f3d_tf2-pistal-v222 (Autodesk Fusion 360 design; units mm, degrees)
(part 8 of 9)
sketch "Sketch178" plane through (0, 168, 0) normal (0, 1, 0) x axis (-1, 0, 0)
  line L1 (8, 20.5) -> (5, 20.5)
  line L2 (8, 24) -> (8, 20.5)
  line L3 (-8, 24) -> (8, 24)
  line L4 (-8, 20.5) -> (-8, 24)
  line L5 (-5, 20.5) -> (-8, 20.5)
  line L6 (-5, 19.3242) -> (-5, 20.5)
  line L7 (-3.5547, 19.0544) -> (-5.3513, 19.0544)
  line L8 (5.3513, 19.0544) -> (3.5547, 19.0544)
  line L9 (5, 20.5) -> (5, 19.3242)
  line L10 (8, 24) -> (-8, 24)
  line L11 (8, 20.5) -> (8, 24)
  line L12 (-8, 20.5) -> (8, 20.5)
  line L13 (-8, 24) -> (-8, 20.5)
  arc A1 centre (0, 12.4503) radius 8.5 clockwise from (-5.3513, 19.0544) to (-5, 19.3242)
  arc A2 centre (0, 12.4503) radius 7.5 clockwise from (-3.5547, 19.0544) to (3.5547, 19.0544)
  arc A3 centre (0, 12.4503) radius 8.5 clockwise from (5, 19.3242) to (5.3513, 19.0544)
  point P3 (8, 20.5)
  point P17 (8, 20.5)
  point P5 (-8, 24)
  point P15 (-8, 24)
  horizontal L10
  vertical L11
  horizontal L12
  vertical L13
  coincident P3 P17
  coincident P5 P15
extrude "Extrude183" add sketch "Sketch178" profile of L1 L2 L3 L4 L5 L10 L11 L12 L13 along normal blind 20
move_face "MoveFace284"
move_face "MoveFace285"
delete_face "DeleteFace138"
delete_face "DeleteFace139"
fillet "Fillet185" radius 0.4
move_face "MoveFace286"
sketch "Sketch179" plane through (12, 0, 0) normal (1, 0, 0) x axis (0, 1, 0)
  line L1 (170, -7.8255) -> (170, 18)
  line L2 (232.487, -7.8255) -> (170, -7.8255)
  line L3 (212.6935, 18) -> (232.487, -7.8255)
  line L4 (170, 18) -> (212.6935, 18)
  line L5 (199.0187, 27.3514) -> (199.0187, 18.4836)
  vertical L5
split "Split57"
combine "Combine152"
delete_face "DeleteFace140"
delete_face "DeleteFace141"
move_face "MoveFace287"
sketch "Sketch180" plane through (0, 208, 0) normal (0, 1, 0) x axis (-1, 0, 0)
  line L1 (8, 20.5) -> (-8, 20.5)
  line L2 (8, 24) -> (8, 20.5)
  line L3 (-8, 24) -> (8, 24)
  line L4 (-8, 20.5) -> (-8, 24)
  line L5 (5.5, 20.5) -> (5, 20.5)
  line L6 (8, 20.5) -> (5.5, 20.5)
  line L7 (-8, 20.5) -> (8, 20.5)
  line L8 (-5.5, 20.5) -> (-8, 20.5)
  line L9 (-5, 20.5) -> (-5.5, 20.5)
  line L10 (5, 20.5) -> (-5, 20.5)
  line L11 (5.5, 19.5742) -> (5.5, 20.5)
  line L12 (5.5, 20.5) -> (5.5, 19.5742)
  line L13 (5.6661, 19.4429) -> (5.6726, 19.4376)
  curve K1 (5.6726, 19.4376) -> (7.0853, 18)
  line L14 (7.0853, 18) -> (7.0945, 17.9882)
  line L15 (7.0945, 17.9882) -> (7.0853, 18)
  line L16 (-7.0853, 18) -> (-7.0945, 17.9882)
  line L17 (-7.0853, 18) -> (-7.0945, 17.9882)
  curve K2 (-7.0853, 18) -> (-5.6726, 19.4376)
  line L18 (-5.6726, 19.4376) -> (-5.6661, 19.4429)
  line L19 (-8, 20.5) -> (-8, 24)
  line L20 (-8, 24) -> (-8, 20.5)
  line L21 (-8, 24) -> (8, 24)
  line L22 (8, 24) -> (-8, 24)
  line L23 (-5.5, 20.5) -> (-5.5, 19.5742)
  line L24 (-5.5, 19.5742) -> (-5.5, 20.5)
  line L25 (-10, 18) -> (-9.9125, 18)
  line L26 (-7.0853, 18) -> (-9.9125, 18)
  line L27 (-10, 18) -> (-7.0853, 18)
  line L28 (7.0853, 18) -> (10, 18)
  line L29 (9.9125, 18) -> (7.0853, 18)
  line L30 (9.9125, 18) -> (10, 18)
  line L31 (8, 24) -> (8, 20.5)
  line L32 (8, 20.5) -> (8, 24)
  line L33 (9.974, 18) -> (-10, 18)
  line L34 (9.974, 24.7567) -> (9.974, 18)
  line L35 (-10, 24.7567) -> (9.974, 24.7567)
  line L36 (-10, 18) -> (-10, 24.7567)
  arc A1 centre (0, 12.4503) radius 9 clockwise from (5.5, 19.5742) to (5.6661, 19.4429)
  arc A2 centre (0, 12.4503) radius 9 clockwise from (5.5, 19.5742) to (7.0853, 18)
  arc A3 centre (0, 12.4503) radius 9 clockwise from (-5.6661, 19.4429) to (-5.5, 19.5742)
  arc A4 centre (0, 12.4503) radius 9 clockwise from (-7.0853, 18) to (-5.5, 19.5742)
  point P33 (-10, 18)
  point P41 (-10, 18)
  horizontal L33
  vertical L34
  horizontal L35
  vertical L36
  coincident P33 P41
extrude "Extrude184" add sketch "Sketch180" profile of L1 L5 L7 L9 L10 L11 L12 A1 L13 K1 A2 A3 A4 K2 L18 L23 L24 L33 along normal blind 8 and against normal blind 10
sketch "Sketch181" plane through (12, 0, 0) normal (1, 0, 0) x axis (0, 1, 0)
  line L1 (212.6935, 18) -> (232.487, -7.8255)
  line L2 (170, 18) -> (212.6935, 18)
  line L3 (170, 16) -> (170, 18)
  line L4 (61.1873, 16) -> (170, 16)
  line L5 (61.1873, -0.0135) -> (61.1873, 16)
  curve K1 (94.4938, -16.1797) -> (61.1873, -0.0135)
  line L6 (140.7785, -16.1797) -> (94.4938, -16.1797)
  curve K2 (160.0503, -33.0679) -> (140.7785, -16.1797)
  line L7 (180.741, -100.6968) -> (160.0503, -33.0679)
  line L8 (176.9575, -112.7565) -> (180.741, -102.825)
  line L9 (180.6935, -126.5461) -> (176.9575, -112.7565)
  line L10 (252.3821, -107.1238) -> (180.6935, -126.5461)
  curve K3 (218.6662, -36.3833) -> (252.3821, -107.1238)
  line L11 (218.6662, -22.9466) -> (218.6662, -36.3833)
  line L12 (232.2171, -10.7508) -> (218.6662, -22.9466)
  line L13 (232.487, -7.8255) -> (232.2171, -10.7508)
  line L14 (153.8679, 8.2929) -> (153.8679, 3.9459)
  line L15 (152.8679, 9.7071) -> (153.575, 9)
  line L16 (102, 10) -> (152.1608, 10)
  line L17 (100, 13) -> (100, 12)
  line L18 (156.3679, 15) -> (102, 15)
  line L19 (158.8679, 3.3459) -> (158.8679, 12.5)
  line L20 (154.8679, 2.9459) -> (158.4679, 2.9459)
  line L21 (208, -7.8255) -> (235.9291, -7.8255)
  line L22 (208, 36) -> (208, -7.8255)
  line L23 (235.9291, -7.8255) -> (208, 36)
  arc A1 centre (177.9477, -101.7609) radius 2.9891 clockwise from (180.741, -100.6968) to (180.741, -102.825)
  circle C1 centre (80, -5) radius 4
  arc A2 centre (152.8679, 8.2929) radius 1 clockwise from (153.575, 9) to (153.8679, 8.2929)
  arc A3 centre (152.1608, 9) radius 1 clockwise from (152.1608, 10) to (152.8679, 9.7071)
  arc A4 centre (102, 12) radius 2 clockwise from (102, 10) to (100, 12)
  arc A5 centre (102, 13) radius 2 clockwise from (100, 13) to (102, 15)
  arc A6 centre (156.3679, 12.5) radius 2.5 clockwise from (156.3679, 15) to (158.8679, 12.5)
  arc A7 centre (158.4679, 3.3459) radius 0.4 clockwise from (158.8679, 3.3459) to (158.4679, 2.9459)
  arc A8 centre (154.8679, 3.9459) radius 1 clockwise from (154.8679, 2.9459) to (153.8679, 3.9459)
  parallel L2 L21
  perpendicular L21 L22
extrude "Extrude185" cut sketch "Sketch181" profile of L1 L2 L21 L22 L23 against normal blind 80
move_face "MoveFace289"
delete_face "DeleteFace142"
move_face "MoveFace290"
fillet "Fillet186" radius 0.5
fillet "Fillet187" radius 0.5
fillet "Fillet188" radius 2
sketch "Sketch182" plane through (0, 61.1873, 0) normal (0, -1, 0) x axis (1, 0, 0)
  line L1 (7.0853, 18) -> (10, 18)
  line L2 (5.5, 20.5) -> (5.5, 19.5742)
  line L3 (8, 20.5) -> (5.5, 20.5)
  line L4 (8, 24) -> (8, 20.5)
  line L5 (-8, 24) -> (8, 24)
  line L6 (-8, 20.5) -> (-8, 24)
  line L7 (-5.5, 20.5) -> (-8, 20.5)
  line L8 (-5.5, 19.5742) -> (-5.5, 20.5)
  line L9 (-10, 18) -> (-7.0853, 18)
  line L10 (-12, -0.0135) -> (-12, 16)
  line L11 (12, -0.0135) -> (-12, -0.0135)
  line L12 (12, 16) -> (12, -0.0135)
  arc A1 centre (10, 16) radius 2 clockwise from (10, 18) to (12, 16)
  arc A2 centre (0, 12.4503) radius 9 clockwise from (5.5, 19.5742) to (7.0853, 18)
  arc A3 centre (0, 12.4503) radius 9 clockwise from (-7.0853, 18) to (-5.5, 19.5742)
  arc A4 centre (-10, 16) radius 2 clockwise from (-12, 16) to (-10, 18)
  circle C1 centre (0, 12.4503) radius 7
  circle C2 centre (0, 12.4503) radius 7
  circle C3 centre (0, 12.4503) radius 9
  concentric A2 C2
  concentric C2 C3
extrude "Extrude186" add sketch "Sketch182" profile of A2 A3 C1 C2 C3 along normal blind 2
chamfer "Chamfer84" distance 24.487
sketch "Sketch183" plane through (0, 0, 0) normal (1, 0, 0) x axis (0, 1, 0)
  curve K1 (156.3835, -12.3902) -> (138.0168, -12.3902)
  line L1 (157.8154, 1.7369) -> (156.3835, -12.3902)
  line L2 (154.8137, 2.0412) -> (157.8154, 1.7369)
  line L3 (153, -3) -> (154.8137, 2.0412)
  line L4 (146, -5) -> (153, -3)
  line L5 (141.1029, -4) -> (146, -5)
  circle C1 centre (132.9233, -5.754) radius 8.3656
  circle C2 centre (132.9233, -5.754) radius 3.6375
  point P2 (138.0168, -12.3902)
  point P13 (141.1029, -4)
  coincident P2 C1
  perpendicular L1 L2
  coincident C1 P13
  concentric C1 C2
extrude "Extrude187" new body sketch "Sketch183" distance 5
move "Move104"
move "Move105"
delete_face "DeleteFace143"
move_face "MoveFace291"
fillet "Fillet189" radius 2.75
delete_face "DeleteFace144"
delete_face "DeleteFace145"
fillet "Fillet190" radius 1.5
fillet "Fillet191" radius 2.25
sketch "Sketch184" plane through (0, 0, 0) normal (1, 0, 0) x axis (0, 1, 0)
  line L1 (115, -45.5944) -> (115.3754, -45.5944)
  line L2 (104.2312, -16.3305) -> (115, -45.5944)
  line L3 (160.1732, -58.5426) -> (145.9081, -60.7836)
  line L4 (170, -65) -> (160.1732, -58.5426)
  line L5 (172.2622, -64.6446) -> (170, -65)
  line L6 (157.1534, -13.7491) -> (172.2622, -64.6446)
  line L7 (104.2312, -13.7491) -> (157.1534, -13.7491)
  line L8 (104.2312, -16.3305) -> (104.2312, -13.7491)
  circle C1 centre (138.3458, -37.7027) radius 19.2949
  circle C2 centre (138.3458, -37.7027) radius 24.2882
  point P4 (115.3754, -45.5944)
  point P7 (145.9081, -60.7836)
  concentric C1 C2
  coincident C2 P4
  horizontal L1
  coincident C2 P7
  parallel L3 L5
  horizontal L7
  perpendicular L7 L8
extrude "Extrude188" new body sketch "Sketch184" distance 8
move_face "MoveFace292"
fillet "Fillet192" radius 11.5
delete_face "DeleteFace146"
combine "Combine153"
fillet "Fillet193" radius 7.5
fillet "Fillet194" radius 2
fillet "Fillet195" radius 2.5
fillet "Fillet196" radius 12
fillet "Fillet197" radius 9
sketch "Sketch185" plane through (-12, 0, 0) normal (-1, 0, 0) x axis (0, -1, 0)
  line L1 (-94.4938, -16.1797) -> (-164.2952, -16.1797)
  curve K1 (-61.1873, -0.0135) -> (-94.4938, -16.1797)
  line L2 (-61.1873, 16) -> (-61.1873, -0.0135)
  line L3 (-208.6615, 16) -> (-61.1873, 16)
  line L4 (-221.4542, 3.2073) -> (-208.6615, 16)
  line L5 (-220.6993, -4.9724) -> (-221.4542, 3.2073)
  line L6 (-206.6662, -17.6022) -> (-220.6993, -4.9724)
  line L7 (-206.6662, -40.176) -> (-206.6662, -17.6022)
  curve K2 (-206.6662, -40.176) -> (-240.729, -110.2809)
  line L8 (-189.3803, -124.1926) -> (-240.729, -110.2809)
  line L9 (-186.4094, -113.2266) -> (-189.3803, -124.1926)
  line L10 (-189.1513, -106.0289) -> (-186.4094, -113.2266)
  line L11 (-164.2952, -16.1797) -> (-189.2884, -97.8715)
  line L12 (-156.6179, 2.9459) -> (-154.8679, 2.9459)
  line L13 (-158.8679, 12.5) -> (-158.8679, 5.1959)
  line L14 (-102, 15) -> (-156.3679, 15)
  line L15 (-100, 12) -> (-100, 13)
  line L16 (-150.7288, 10) -> (-102, 10)
  line L17 (-153.0624, 8.8055) -> (-152.6733, 9.1945)
  line L18 (-153.8679, 3.9459) -> (-153.8679, 6.8609)
  line L19 (-164.2952, -16.1797) -> (-94.4938, -16.1797)
  line L20 (-189.2884, -97.8715) -> (-164.2952, -16.1797)
  curve K3 (-171.2455, -38.897) -> (-143.3956, -16.1797)
  curve K4 (-147.7912, -17.3594) -> (-139, -15)
  arc A1 centre (-177.9477, -101.7609) radius 11.9891 clockwise from (-189.1513, -106.0289) to (-189.2884, -97.8715)
  circle C1 centre (-80, -5) radius 4
  arc A2 centre (-156.6179, 5.1959) radius 2.25 clockwise from (-156.6179, 2.9459) to (-158.8679, 5.1959)
  arc A3 centre (-156.3679, 12.5) radius 2.5 clockwise from (-158.8679, 12.5) to (-156.3679, 15)
  arc A4 centre (-102, 13) radius 2 clockwise from (-102, 15) to (-100, 13)
  arc A5 centre (-102, 12) radius 2 clockwise from (-100, 12) to (-102, 10)
  arc A6 centre (-150.7288, 7.25) radius 2.75 clockwise from (-152.6733, 9.1945) to (-150.7288, 10)
  arc A7 centre (-151.1179, 6.8609) radius 2.75 clockwise from (-153.8679, 6.8609) to (-153.0624, 8.8055)
  arc A8 centre (-154.8679, 3.9459) radius 1 clockwise from (-153.8679, 3.9459) to (-154.8679, 2.9459)
  point P42 (-143.3956, -16.1797)
  point P45 (-171.2455, -38.897)
  coincident L19 P42
  coincident L20 P45
  midpoint P42 K4
extrude "Extrude189" new body sketch "Sketch185" profile of L1 L11 L19 L20 K3 against normal blind 4
mirror "Mirror43" mirrorStitchTolerance 0.1
combine "Combine154"
fillet "Fillet198" radius 2.5
fillet "Fillet199" radius 15
chamfer "Chamfer85" distance 1
move_face "MoveFace293"
move_face "MoveFace294"
fillet "Fillet200" radius 4
fillet "Fillet201" radius 1
fillet "Fillet202" radius 1
move_face "MoveFace295"
sketch "Sketch186" plane through (0, 0, 0) normal (1, 0, 0) x axis (0, 1, 0)
  line L1 (152.446, 6.5702) -> (139.9456, 2.0072)
  line L2 (159.6229, 4.8892) -> (152.446, 6.5702)
  curve K1 (155, -30) -> (159.6229, 4.8892)
  curve K2 (143.3256, -19.8355) -> (137.9113, -11.6209)
  line L3 (155, -30) -> (143.3256, -19.8355)
  circle C1 centre (133.5549, -4.0047) radius 3.6375
  circle C2 centre (133.5549, -4.0047) radius 8.7741
  point P5 (139.9456, 2.0072)
  point P10 (137.9113, -11.6209)
  concentric C1 C2
  coincident C2 P5
  coincident C2 P10
extrude "Extrude190" cut sketch "Sketch186" distance 5.2
delete_face "DeleteFace147"
delete_face "DeleteFace148"
sketch "Sketch187" plane through (-5, 0, 0) normal (-1, 0, 0) x axis (0, -1, 0)
  line L1 (-146.65, -3.7075) -> (-141.7908, -2.5372)
  line L2 (-153.7155, -1.953) -> (-146.65, -3.7075)
  line L3 (-155.7041, 3.0218) -> (-153.7155, -1.953)
  line L4 (-158.6933, 2.6129) -> (-155.7041, 3.0218)
  line L5 (-156.7692, -11.4556) -> (-158.6933, 2.6129)
  curve K1 (-138.4137, -10.8146) -> (-156.7692, -11.4556)
  line L6 (-143, -18) -> (-160, -12)
  line L7 (-145.0135, -29) -> (-145.0135, -17.2894)
  line L8 (-139.9494, -46.8713) -> (-145.0135, -29)
  line L9 (-146.9651, -39.243) -> (-139.9494, -46.8713)
  line L10 (-154.4003, -23.1447) -> (-146.9651, -39.243)
  line L11 (-155.5267, -13.5788) -> (-154.4003, -23.1447)
  line L12 (-154.4003, -41.7536) -> (-158.6986, -12.4593)
  line L13 (-143.3923, -50.4441) -> (-154.4003, -41.7536)
  line L14 (-133.6396, -50.4441) -> (-143.3923, -50.4441)
  line L15 (-128.9829, -44.5456) -> (-133.6396, -50.4441)
  line L16 (-137.5986, -32.2906) -> (-128.9829, -44.5456)
  line L17 (-143, -18) -> (-137.5986, -32.2906)
  circle C1 centre (-133.5549, -4.0047) radius 3.6375
  arc A1 centre (-133.5549, -4.0047) radius 8.3656 clockwise from (-141.7908, -2.5372) to (-138.4137, -10.8146)
  point P12 (-145.0135, -17.2894)
  point P17 (-155.5267, -13.5788)
  point P18 (-158.6986, -12.4593)
  coincident L6 P12
  vertical L7
  coincident L6 P17
  coincident L6 P18
  horizontal L14
  perpendicular L13 L15
extrude "Extrude191" cut sketch "Sketch187" profile of K1 L6 L7 L8 L9 L10 L11 L12 L13 L14 L15 L16 L17 against normal blind 10
fillet "Fillet203" radius 18.5
fillet "Fillet204" radius 55.5
fillet "Fillet205" radius 2.75
fillet "Fillet206" radius 14
fillet "Fillet207" radius 2
fillet "Fillet208" radius 0.5
fillet "Fillet209" radius 2
fillet "Fillet210" radius 2
fillet "Fillet211" radius 317
fillet "Fillet212" radius 2.5
sketch "Sketch188" plane through (0, 15.8076, -43.3059) normal (0, 0.3429, -0.9394) x axis (-1, 0, 0)
  line L1 (5.2, 146.9606) -> (5.2, 132.1495)
  line L2 (4.4969, 146.9606) -> (5.2, 146.9606)
  line L3 (-5.2, 146.9606) -> (-4.4969, 146.9606)
  line L4 (-5.2, 132.1495) -> (-5.2, 146.9606)
  line L5 (5.2, 132.1495) -> (-5.2, 132.1495)
  line L6 (5.2, 138.788) -> (-5.2, 138.788)
  line L7 (5.2, 145.212) -> (5.2, 138.788)
  line L8 (-5.2, 145.212) -> (5.2, 145.212)
  line L9 (-5.2, 138.788) -> (-5.2, 145.212)
  line L10 (5.2, 145.212) -> (-5.2, 138.788)
  line L11 (-5.2, 145.212) -> (5.2, 138.788)
  line L12 (5.2, 147.6213) -> (-5.2, 147.6213)
  line L13 (5.2, 140.3787) -> (5.2, 147.6213)
  line L14 (-5.2, 140.3787) -> (5.2, 140.3787)
  line L15 (-5.2, 147.6213) -> (-5.2, 140.3787)
  line L16 (5.2, 140.3787) -> (-5.2, 147.6213)
  line L17 (-5.2, 140.3787) -> (5.2, 147.6213)
  closed curve K1 centre (0, 162.6054)
  point P13 (0, 142)
  point P9 (-5.2, 138.788)
  point P18 (0, 144)
  horizontal L6
  perpendicular L6 L7
  parallel L6 L8
  parallel L7 L9
  coincident L10 P13
  coincident L11 P13
  coincident L4 P9
  horizontal L12
  perpendicular L12 L13
  parallel L12 L14
  parallel L13 L15
  coincident L16 P18
  coincident L17 P18
extrude "Extrude192" cut sketch "Sketch188" profile of L1 L2 K1 L3 L4 L7 L8 L9 L12 L13 L14 L15 against normal blind 6
fillet "Fillet213" radius 2
sketch "Sketch189" plane through (0, 208, 0) normal (0, 1, 0) x axis (-1, 0, 0)
  line L1 (11.8874, 16.6615) -> (-11.8874, 16.6615)
  line L2 (7.0853, 18) -> (10, 18)
  line L3 (5.5, 20.5) -> (5.5, 19.5742)
  line L4 (8, 20.5) -> (5.5, 20.5)
  line L5 (8, 24) -> (8, 20.5)
  line L6 (-8, 24) -> (8, 24)
  line L7 (-8, 20.5) -> (-8, 24)
  line L8 (-5.5, 20.5) -> (-8, 20.5)
  line L9 (-5.5, 19.5742) -> (-5.5, 20.5)
  curve K1 (-5.6726, 19.4376) -> (-7.0853, 18)
  line L10 (-10, 18) -> (-7.0853, 18)
  line L11 (-3, 11) -> (3, 11)
  line L12 (-3, 37) -> (-3, 11)
  line L13 (3, 37) -> (-3, 37)
  line L14 (3, 11) -> (3, 37)
  line L15 (-3, 37) -> (3, 11)
  line L16 (3, 37) -> (-3, 11)
  arc A1 centre (10, 16) radius 2 clockwise from (10, 18) to (11.8874, 16.6615)
  arc A2 centre (0, 12.4503) radius 9 clockwise from (5.5, 19.5742) to (7.0853, 18)
  arc A3 centre (0, 12.4503) radius 9 clockwise from (-5.6726, 19.4376) to (-5.5, 19.5742)
  arc A4 centre (-10, 16) radius 2 clockwise from (-11.8874, 16.6615) to (-10, 18)
  point P24 (0, 24)
  horizontal L11
  perpendicular L11 L12
  parallel L11 L13
  parallel L12 L14
  coincident L15 P24
  coincident L16 P24
  midpoint L6 P24
extrude "Extrude193" cut sketch "Sketch189" profile of L1 L6 L11 L12 L13 L14 along normal blind 25 and against normal blind 20
chamfer "Chamfer86" distance 0.5
chamfer "Chamfer87" distance 0.5
move_face "MoveFace296"
sketch "Sketch190" plane through (0, 0, 0) normal (1, 0, 0) x axis (0, 1, 0)
  line L1 (232.6325, -6.7081) -> (207, 27)
  line L2 (100, -6.7081) -> (232.6325, -6.7081)
  curve K1 (70.1883, 6.3275) -> (100, -6.7081)
  curve K2 (63.1691, 6.3275) -> (77.2075, 6.3275)
  line L3 (61, 6.3275) -> (70.1883, 6.3275)
  line L4 (61, 27) -> (61, 6.3275)
  line L5 (213, 27) -> (61, 27)
  point P7 (70.1883, 6.3275)
  point P2 (207, 27)
  horizontal L2
  midpoint P7 K2
  perpendicular L3 L4
  perpendicular L4 L5
  coincident P2 L5
extrude "Extrude194" new body sketch "Sketch190" profile of L1 L2 K1 L3 L4 L5 distance 14
shell "Shell2" innerThickness 1.5
fillet "Fillet214" radius 12
fillet "Fillet215" radius 2.5
move_face "MoveFace297"
fillet "Fillet216" radius 2.5
fillet "Fillet217" radius 4
fillet "Fillet218" radius 0.5
fillet "Fillet219" radius 1
copy_paste_bodies "CopyPasteBodies15"
offset_faces "OffsetFaces30" distance 1
offset_faces "OffsetFaces31" distance 1
offset_faces "OffsetFaces32" distance 1
sketch "Sketch191" plane through (0, 60, 0) normal (0, -1, 0) x axis (1, 0, 0)
  line L1 (-3, 27.5) -> (3, 27.5)
  line L2 (-14.5, 8.8275) -> (-14.5, 16)
  line L3 (-13, 8.8275) -> (-14.5, 8.8275)
  line L4 (-13, 13.5) -> (-13, 8.8275)
  line L5 (0.5, 26) -> (-0.5, 26)
  line L6 (13, 8.8275) -> (13, 13.5)
  line L7 (14.5, 8.8275) -> (13, 8.8275)
  line L8 (14.5, 16) -> (14.5, 8.8275)
  line L9 (-8.2, 24.2) -> (-8.2, 20.2499)
  line L10 (8.2, 24.2) -> (-8.2, 24.2)
  line L11 (8.2, 20.2499) -> (8.2, 24.2)
  line L12 (-8.2, 24.2) -> (8.2, 20.2499)
  line L13 (8.2, 24.2) -> (-8.2, 20.2499)
  line L14 (8, 24) -> (8, 20.5)
  line L15 (-8, 20.5) -> (-8, 24)
  line L16 (-8, 24) -> (8, 24)
  line L17 (-8.2, 20.3) -> (8.2, 20.3)
  line L18 (3.5, 20.5) -> (-3.5, 20.5)
  line L19 (5.5, 20.5) -> (3.5, 20.5)
  line L20 (8, 20.5) -> (5.5, 20.5)
  line L21 (5.5, 20.5) -> (8, 20.5)
  line L22 (5.5, 20.5) -> (5, 20.5)
  line L23 (-5, 20.5) -> (5, 20.5)
  line L24 (-5, 20.5) -> (-5.5, 20.5)
  line L25 (-8, 20.5) -> (-5.5, 20.5)
  line L26 (-5.5, 20.5) -> (-8, 20.5)
  line L27 (-3.5, 20.5) -> (-5.5, 20.5)
  line L28 (-5.7, 19) -> (-5.7, 20.3)
  line L29 (5.7, 19) -> (5.7, 20.3)
  line L30 (-5.5, 19.5742) -> (-5.5, 20.5)
  line L31 (5.5, 20.5) -> (5.5, 19.5742)
  line L32 (17.4528, 18.2) -> (-12.686, 18.2)
  line L33 (18.2375, 18.4672) -> (17.4528, 18.2)
  line L34 (7.0853, 18) -> (10, 18)
  line L35 (10, 18.2) -> (5.7, 19.65)
  line L36 (-10, 18) -> (-7.0853, 18)
  line L37 (-10, 18.2) -> (-5.7, 19.65)
  arc A1 centre (3, 16) radius 11.5 clockwise from (3, 27.5) to (14.5, 16)
  arc A2 centre (-3, 16) radius 11.5 clockwise from (-14.5, 16) to (-3, 27.5)
  arc A3 centre (-0.5, 13.5) radius 12.5 clockwise from (-13, 13.5) to (-0.5, 26)
  arc A4 centre (0.5, 13.5) radius 12.5 clockwise from (0.5, 26) to (13, 13.5)
  circle C1 centre (0, 12.4503) radius 9
  circle C2 centre (0, 12.4503) radius 9.2
  point P22 (0, 22.225)
  point P27 (8.2, 20.3)
  point P28 (-8.2, 20.3)
  point P37 (-5.7, 20.3)
  point P39 (5.7, 20.3)
  point P52 (5.7, 19.65)
  point P53 (10, 18.2)
  point P56 (-5.7, 19.65)
  point P57 (-10, 18.2)
  point P29 (-3.5, 20.5)
  parallel L9 L11
  coincident L12 P22
  coincident L13 P22
  coincident L11 P27
  coincident L9 P28
  perpendicular L9 L17
  coincident L17 P37
  perpendicular L17 L28
  coincident L17 P39
  perpendicular L17 L29
  concentric C1 C2
  horizontal L32
  midpoint L29 P52
  coincident L32 P53
  midpoint L28 P56
  coincident L32 P57
  dimension "d1533" distance L11 L14 = 0.2
  dimension "d1534" distance L9 L15 = 0.2
  dimension "d1535" distance L10 L16 = 0.2
  dimension "d1536" distance L17 P29 = 0.2
  dimension "d1537" distance L28 L30 = 0.2
  dimension "d1538" distance L29 L31 = 0.2
  dimension "d1539" distance C1 C2 = 0.2
  dimension "d1540" distance L32 L34 = 0.2
extrude "Extrude195" new body sketch "Sketch191" profile of A3 L5 A4 L9 L10 L11 L17 L28 L29 C2 L32 L35 L37 against normal blind 147
split "Split58"
split "Split59"
remove_body "RemoveBody87"
remove_body "RemoveBody88"
combine "Combine155"
delete_face "DeleteFace149"
delete_face "DeleteFace150"
chamfer "Chamfer88" distance 2
chamfer "Chamfer89" distance 0.5
sketch "Sketch192" plane through (0, 0, 0) normal (1, 0, 0) x axis (0, 1, 0)
  line L1 (200, 11.142) -> (154, 11.142)
  line L2 (200, 17.483) -> (200, 11.142)
  line L3 (154, 17.483) -> (200, 17.483)
  line L4 (154, 11.142) -> (154, 17.483)
  line L5 (207, 24.2) -> (207.2241, 24.2)
  line L6 (60, 24.2) -> (207, 24.2)
  line L7 (207, 24.2) -> (60, 24.2)
  line L8 (207, 24.2) -> (207.2241, 24.2)
  line L9 (188.1902, 24.2) -> (207, 24.2)
  line L10 (188.1902, 11.142) -> (188.1902, 24.2)
  line L11 (207, 11.142) -> (188.1902, 11.142)
  line L12 (207, 24.2) -> (207, 11.142)
  point P11 (188.1902, 11.142)
  point P7 (207, 24.2)
  point P9 (207, 24.2)
  horizontal L1
  vertical L2
  horizontal L3
  vertical L4
  horizontal L9
  vertical L10
  horizontal L11
  vertical L12
  coincident L1 P11
  coincident P7 P9
extrude "Extrude196" new body sketch "Sketch192" profile of L1 L2 L3 L4 L6 L7 L9 L10 L11 L12 distance 3
sketch "Sketch193" plane through (-15, 0, 0) normal (-1, 0, 0) x axis (0, -1, 0)
  line L1 (-227.2272, -6.2081) -> (-210.3395, 16)
  line L2 (-101.5272, -6.2081) -> (-227.2272, -6.2081)
  curve K1 (-101.5272, -6.2081) -> (-99.7709, -5.1649)
  curve K2 (-99.7709, -5.1649) -> (-70.1883, 6.8275)
  line L3 (-62.5, 6.8275) -> (-70.1883, 6.8275)
  line L4 (-60.5, 16) -> (-60.5, 8.8275)
  line L5 (-210.3395, 16) -> (-60.5, 16)
  line L6 (-100.4605, 14.9736) -> (-159.0253, 14.9736)
  line L7 (-159.0253, 14.9736) -> (-159.0253, 2.7844)
  line L8 (-98.1178, 2.9961) -> (-98.1314, 6.9148)
  line L9 (-100.4605, 14.9736) -> (-98.1314, 6.9148)
  line L10 (-98.1178, 2.9961) -> (-159.0253, 2.7844)
  arc A1 centre (-62.5, 8.8275) radius 2 clockwise from (-60.5, 8.8275) to (-62.5, 6.8275)
  horizontal L6
  vertical L7
  perpendicular L8 L10
split "Split60"
fillet "Fillet220" radius 2
fillet "Fillet221" radius 2
fillet "Fillet222" radius 2.5
fillet "Fillet223" radius 2.25
move_face "MoveFace298"
move_face "MoveFace299"
chamfer "Chamfer90" distance 0.5
split "Split61"
delete_face "DeleteFace151"
fillet "Fillet224" radius 59
move_face "MoveFace300"
move_face "MoveFace301"
move_face "MoveFace302"
sketch "Sketch194" plane through (0, 0, 0) normal (-1, 0, 0) x axis (0, -1, 0)
  line L1 (-212.6009, 10.6464) -> (-211.7473, 11)
  line L2 (-231.0728, -7.8255) -> (-212.6009, 10.6464)
  line L3 (-231.3905, -7.8255) -> (-231.0728, -7.8255)
  curve K1 (-231.3905, -7.8255) -> (-232.3863, -8.9174)
  line L4 (-232.2171, -10.7508) -> (-232.3863, -8.9174)
  line L5 (-218.6662, -22.9466) -> (-232.2171, -10.7508)
  line L6 (-218.6662, -36.3833) -> (-218.6662, -22.9466)
  curve K2 (-252.0162, -106.1931) -> (-218.6662, -36.3833)
  line L7 (-251.4169, -107.3853) -> (-252.0162, -106.1931)
  line L8 (-235.1318, -111.7973) -> (-251.4169, -107.3853)
  line L9 (-201.3197, 10.517) -> (-233.9044, -111.0909)
  line L10 (-201.6902, 11) -> (-201.3197, 10.517)
  line L11 (-211.7473, 11) -> (-201.6902, 11)
  line L12 (-204.3927, -0.9518) -> (-224.1991, -0.9518)
  line L13 (-204.3927, -0.9518) -> (-212.5827, -31.5171)
  line L14 (-211.4843, -31.8114) -> (-212.5827, -31.5171)
  line L15 (-212.4984, -35.596) -> (-211.4843, -31.8114)
  line L16 (-215.7362, -34.7285) -> (-212.4984, -35.596)
  line L17 (-207.5956, -4.3472) -> (-215.7362, -34.7285)
  line L18 (-213.8018, -4.3472) -> (-207.5956, -4.3472)
  line L19 (-225.4416, -16.8487) -> (-213.8018, -4.3472)
  line L20 (-217, -17) -> (-213.8018, -4.3472)
  line L21 (-217, -39) -> (-217, -17)
  line L22 (-214.7493, -39.6031) -> (-217, -39)
  arc A1 centre (-234.8703, -110.8321) radius 1 clockwise from (-233.9044, -111.0909) to (-235.1318, -111.7973)
  point P17 (-224.1991, -0.9518)
  point P18 (-204.3927, -0.9518)
  point P19 (-212.5827, -31.5171)
  point P25 (-225.4416, -16.8487)
  point P28 (-214.7493, -39.6031)
  coincident L2 P17
  coincident L9 P18
  horizontal L12
  coincident L9 P19
  parallel L9 L13
  perpendicular L9 L14
  perpendicular L14 L15
  perpendicular L15 L16
  perpendicular L16 L17
  horizontal L18
  midpoint L5 P25
  parallel L6 L21
  coincident L9 P28
  perpendicular L9 L22
extrude "Extrude197" cut sketch "Sketch194" profile of L9 L16 L17 L18 L20 L21 L22 distance 5
sketch "Sketch195" plane through (0, 60, 0) normal (0, -1, 0) x axis (1, 0, 0)
  line L1 (8.2, 24.2) -> (-8.2, 24.2)
  line L2 (8.2, 20.3) -> (8.2, 24.2)
  line L3 (5.7, 20.3) -> (8.2, 20.3)
  line L4 (5.7, 19.6718) -> (5.7, 20.3)
  line L5 (10, 18.2) -> (5.7476, 19.6339)
  line L6 (12.0827, 18.2) -> (10, 18.2)
  line L7 (13, 8.8275) -> (13, 13.5)
  line L8 (14.5, 8.8275) -> (13, 8.8275)
  line L9 (14.5, 16) -> (14.5, 8.8275)
  line L10 (-3, 27.5) -> (3, 27.5)
  line L11 (-14.5, 8.8275) -> (-14.5, 16)
  line L12 (-13, 8.8275) -> (-14.5, 8.8275)
  line L13 (-13, 13.5) -> (-13, 8.8275)
  line L14 (-10, 18.2) -> (-12.0827, 18.2)
  line L15 (-5.7476, 19.6339) -> (-10, 18.2)
  line L16 (-5.7, 20.3) -> (-5.7, 19.6718)
  line L17 (-8.2, 20.3) -> (-5.7, 20.3)
  line L18 (-8.2, 24.2) -> (-8.2, 20.3)
  line L19 (-8.2, 18.4441) -> (-8.2, 20.3)
  line L20 (8.2, 18.3692) -> (8.2, 20.3)
  arc A1 centre (0, 12.4503) radius 9.2 clockwise from (5.7, 19.6718) to (5.7476, 19.6339)
  arc A2 centre (0.5, 13.5) radius 12.5 clockwise from (12.0827, 18.2) to (13, 13.5)
  arc A3 centre (3, 16) radius 11.5 clockwise from (3, 27.5) to (14.5, 16)
  arc A4 centre (-3, 16) radius 11.5 clockwise from (-14.5, 16) to (-3, 27.5)
  arc A5 centre (-0.5, 13.5) radius 12.5 clockwise from (-13, 13.5) to (-12.0827, 18.2)
  arc A6 centre (0, 12.4503) radius 9.2 clockwise from (-5.7476, 19.6339) to (-5.7, 19.6718)
  point P30 (-8.2, 20.3)
  point P31 (-8.2, 20.3)
  point P4 (8.2, 20.3)
  point P33 (8.2, 20.3)
  coincident P30 P31
  perpendicular L17 L19
  coincident P4 P33
  perpendicular L3 L20
extrude "Extrude198" cut sketch "Sketch195" profile of L3 L4 A1 L5 L15 A6 L16 L17 L19 L20 against normal blind 1.187
fillet "Fillet225" radius 0.5
delete_face "DeleteFace152"
delete_face "DeleteFace153"
delete_face "DeleteFace154"
delete_face "DeleteFace155"
fillet "Fillet226" radius 5
fillet "Fillet227" radius 9.5
fillet "Fillet228" radius 1
fillet "Fillet229" radius 1
fillet "Fillet230" radius 0.5
fillet "Fillet231" radius 0.5
delete_face "DeleteFace156"
delete_face "DeleteFace157"
chamfer "Chamfer91" distance 8
sketch "Sketch196" plane through (0, 60, 0) normal (0, -1, 0) x axis (1, 0, 0)
  line L1 (7, 28) -> (15, 20)
  line L2 (-7, 28) -> (7, 28)
  line L3 (-15, 20) -> (-7, 28)
  line L4 (-15, 8.8275) -> (-15, 20)
  line L5 (-12.5, 8.8275) -> (-15, 8.8275)
  line L6 (-12.5, 13.5) -> (-12.5, 8.8275)
  line L7 (-10, 18.2) -> (-11.5413, 18.2)
  line L8 (-8.2, 18.807) -> (-10, 18.2)
  line L9 (-8.2, 24.2) -> (-8.2, 18.807)
  line L10 (8.2, 24.2) -> (-8.2, 24.2)
  line L11 (8.2, 18.807) -> (8.2, 24.2)
  line L12 (10, 18.2) -> (8.2, 18.807)
  line L13 (11.5413, 18.2) -> (10, 18.2)
  line L14 (12.5, 8.8275) -> (12.5, 13.5)
  line L15 (15, 8.8275) -> (12.5, 8.8275)
  line L16 (15, 20) -> (15, 8.8275)
  arc A1 centre (-0.5, 13.5) radius 12 clockwise from (-12.5, 13.5) to (-11.5413, 18.2)
  arc A2 centre (0.5, 13.5) radius 12 clockwise from (11.5413, 18.2) to (12.5, 13.5)
  circle C1 centre (0, 40) radius 13.0036
extrude "Extrude199" cut sketch "Sketch196" profile of L2 C1 against normal blind 160
chamfer "Chamfer92" distance 5
fillet "Fillet232" radius 10
fillet "Fillet233" radius 0.5
fillet "Fillet234" radius 0.5
sketch "Sketch197" plane through (-12, 0, 0) normal (-1, 0, 0) x axis (0, -1, 0)
  line L1 (-221.2152, 0.6179) -> (-205.8331, 16)
  line L2 (-220.6993, -4.9724) -> (-221.2152, 0.6179)
  line L3 (-206.6662, -17.6022) -> (-220.6993, -4.9724)
  line L4 (-206.6662, -40.176) -> (-206.6662, -17.6022)
  curve K1 (-206.6662, -40.176) -> (-240.3598, -109.3449)
  line L5 (-189.1188, -123.2274) -> (-240.3598, -109.3449)
  line L6 (-186.4094, -113.2266) -> (-189.1188, -123.2274)
  line L7 (-189.1513, -106.0289) -> (-186.4094, -113.2266)
  line L8 (-169.5112, -33.2283) -> (-189.2884, -97.8715)
  curve K2 (-169.5112, -33.2283) -> (-143.7253, -13.6797)
  line L9 (-94.4207, -13.6797) -> (-143.7253, -13.6797)
  curve K3 (-94.4207, -13.6797) -> (-61.1873, 4.4251)
  line L10 (-61.1873, 16) -> (-61.1873, 4.4251)
  line L11 (-205.8331, 16) -> (-61.1873, 16)
  line L12 (-152.7089, 8.4519) -> (-152.3198, 8.841)
  line L13 (-153.3679, 3.9459) -> (-153.3679, 6.8609)
  line L14 (-156.6179, 2.4459) -> (-154.8679, 2.4459)
  line L15 (-159.3679, 12.5) -> (-159.3679, 5.1959)
  line L16 (-102, 15.5) -> (-156.3679, 15.5)
  line L17 (-99.5, 12) -> (-99.5, 13)
  line L18 (-150.7288, 9.5) -> (-102, 9.5)
  line L19 (-207.9923, -10) -> (-210, -10)
  line L20 (-156.9952, -10) -> (-207.9923, -10)
  line L21 (-162.573, -10) -> (-190.5399, -101.9622)
  line L22 (-189.1513, -109.6278) -> (-190.5399, -101.9622)
  line L23 (-191.7368, -118.1293) -> (-189.1513, -109.6278)
  line L24 (-242.7117, -102.6271) -> (-191.7368, -118.1293)
  line L25 (-210.775, -33.2696) -> (-242.7117, -102.6271)
  line L26 (-210, -10) -> (-210.775, -33.2696)
  circle C1 centre (-80, -5) radius 4
  arc A1 centre (-177.9477, -101.7609) radius 11.9891 clockwise from (-189.1513, -106.0289) to (-189.2884, -97.8715)
  arc A2 centre (-150.7288, 7.25) radius 2.25 clockwise from (-152.3198, 8.841) to (-150.7288, 9.5)
  arc A3 centre (-151.1179, 6.8609) radius 2.25 clockwise from (-153.3679, 6.8609) to (-152.7089, 8.4519)
  arc A4 centre (-154.8679, 3.9459) radius 1.5 clockwise from (-153.3679, 3.9459) to (-154.8679, 2.4459)
  arc A5 centre (-156.6179, 5.1959) radius 2.75 clockwise from (-156.6179, 2.4459) to (-159.3679, 5.1959)
  arc A6 centre (-156.3679, 12.5) radius 3 clockwise from (-159.3679, 12.5) to (-156.3679, 15.5)
  arc A7 centre (-102, 13) radius 2.5 clockwise from (-102, 15.5) to (-99.5, 13)
  arc A8 centre (-102, 12) radius 2.5 clockwise from (-99.5, 12) to (-102, 9.5)
  point P44 (-162.573, -10)
  horizontal L19
  parallel L19 L20
  coincident L20 P44
  parallel L21 L23
  perpendicular L23 L24
extrude "Extrude200" new body sketch "Sketch197" profile of L3 L4 K1 A1 L19 L20 L21 L22 L23 L24 L25 L26 along normal blind 1 and against normal blind 1
combine "Combine156"
fillet "Fillet235" radius 4.5
fillet "Fillet236" radius 2
move_face "MoveFace303"
fillet "Fillet237" radius 7
extrude "Extrude201" add of existing geometry blind 1
delete_face "DeleteFace158"
fillet "Fillet238" radius 2
sketch "Sketch198" plane through (-14, 0, 0) normal (-1, 0, 0) x axis (0, -1, 0)
  line L1 (-191.5572, -110.665) -> (-193.4854, -117.0054)
  line L2 (-192.5941, -101.8429) -> (-191.421, -108.319)
  line L3 (-166.2531, -15.2274) -> (-192.5941, -101.8429)
  line L4 (-205.6474, -12) -> (-168.645, -12)
  line L5 (-208.7895, -33.7396) -> (-208.146, -14.4168)
  line L6 (-241.0868, -103.8801) -> (-208.7895, -33.7396)
  line L7 (-193.4854, -117.0054) -> (-241.0868, -103.8801)
  arc A1 centre (-196.3409, -109.2102) radius 5 clockwise from (-191.421, -108.319) to (-191.5572, -110.665)
  arc A2 centre (-168.645, -14.5) radius 2.5 clockwise from (-168.645, -12) to (-166.2531, -15.2274)
  arc A3 centre (-205.6474, -14.5) radius 2.5 clockwise from (-208.146, -14.4168) to (-205.6474, -12)
  circle C1 centre (-205.3592, -68.1791) radius 13.0992
extrude "Extrude202" cut sketch "Sketch198" profile of C1 against normal blind 1
chamfer "Chamfer93" distance 1
fillet "Fillet239" radius 0.5
offset_faces "OffsetFaces33" distance -0.2
sketch "Sketch199" plane through (5.2, 0, 0) normal (-1, 0, 0) x axis (0, -1, 0)
  line L1 (-153.3679, 3.9459) -> (-153.3679, 6.8609)
  line L2 (-156.6179, 2.4459) -> (-154.8679, 2.4459)
  line L3 (-159.7699, -1.0651) -> (-158.9914, 1.8404)
  curve K1 (-159.7699, -1.0651) -> (-159.3334, -8.2801)
  curve K2 (-157.6396, -37.9016) -> (-159.3334, -8.2801)
  curve K3 (-141.7435, -14.4954) -> (-139.5542, -18.4457)
  curve K4 (-141.7435, -14.4954) -> (-137.9113, -11.6209)
  line L4 (-147.6758, 4.8289) -> (-139.9456, 2.0072)
  line L5 (-147.3249, 5.7903) -> (-147.6758, 4.8289)
  curve K5 (-144.9641, 7.7641) -> (-147.3249, 5.7903)
  line L6 (-153.1786, 7.7641) -> (-144.9641, 7.7641)
  arc A1 centre (-151.1179, 6.8609) radius 2.25 clockwise from (-153.3679, 6.8609) to (-153.1786, 7.7641)
  arc A2 centre (-154.8679, 3.9459) radius 1.5 clockwise from (-153.3679, 3.9459) to (-154.8679, 2.4459)
  arc A3 centre (-156.6179, 5.1959) radius 2.75 clockwise from (-156.6179, 2.4459) to (-158.0764, 2.8646)
  arc A4 centre (-157.5191, 1.4459) radius 1.5242 clockwise from (-158.9914, 1.8404) to (-158.0764, 2.8646)
  arc A5 centre (-138.3458, -37.7027) radius 19.2949 clockwise from (-157.6396, -37.9016) to (-139.5542, -18.4457)
  arc A6 centre (-133.5549, -4.0047) radius 8.7741 clockwise from (-139.9456, 2.0072) to (-137.9113, -11.6209)
  circle C1 centre (-133.5549, -4.0047) radius 3.2417
  concentric A6 C1
extrude "Extrude203" new body sketch "Sketch199" profile of C1 along normal blind 5.2 bodies "Spacer"
mirror "Mirror44" mirrorStitchTolerance 0.1
extrude "Extrude204" add of existing geometry blind 2
extrude "Extrude205" add of existing geometry blind 2
sketch "Sketch200" plane through (-7.2, 0, 0) normal (-1, 0, 0) x axis (0, -1, 0)
  circle C1 centre (-133.5549, -4.0047) radius 3.3487
extrude "Extrude206" cut sketch "Sketch200" against normal blind 14.4
remove_body "RemoveBody89"
remove_body "RemoveBody90"
remove_body "RemoveBody91"
remove_body "RemoveBody92"
remove_body "RemoveBody93"
sketch "Sketch201" plane through (0, 0, 0) normal (1, 0, 0) x axis (0, 1, 0)
  line L1 (235.4811, 5) -> (235.4811, 8.5401)
  line L2 (227.3196, 5) -> (235.4811, 5)
  line L3 (223, 0) -> (227.3196, 5)
  line L4 (215, 3) -> (223, 0)
  line L5 (220.6186, 9.5036) -> (215, 3)
  line L6 (235.4811, 9.5036) -> (220.6186, 9.5036)
  line L7 (235.4811, 8.5401) -> (235.4811, 9.5036)
  vertical L1
  perpendicular L1 L2
  parallel L3 L5
  parallel L2 L6
  perpendicular L6 L7
extrude "Extrude207" new body sketch "Sketch201" distance 5
sketch "Sketch202" plane through (0, 144.1673, 109.6284) normal (0, 0.796, 0.6053) x axis (-1, 0, 0)
  line L1 (5.8579, -145.1432) -> (-5.8579, -145.1432)
  line L2 (5.8579, -102.7963) -> (5.8579, -145.1432)
  line L3 (5.1086, -102.7963) -> (5.8579, -102.7963)
  line L4 (-5.8579, -102.7963) -> (-5.1086, -102.7963)
  line L5 (-5.8579, -145.1432) -> (-5.8579, -102.7963)
  line L6 (-5.4177, -123.9697) -> (5.4177, -123.9697)
  line L7 (-5.4177, -148.0248) -> (-5.4177, -123.9697)
  line L8 (5.4177, -148.0248) -> (-5.4177, -148.0248)
  line L9 (5.4177, -123.9697) -> (5.4177, -148.0248)
  line L10 (-5.4177, -148.0248) -> (5.4177, -123.9697)
  line L11 (5.4177, -148.0248) -> (-5.4177, -123.9697)
  closed curve K1 centre (0, -87.0927)
  point P13 (0, -135.9973)
  horizontal L6
  perpendicular L6 L7
  parallel L6 L8
  parallel L7 L9
  coincident L10 P13
  coincident L11 P13
split "Split62"
combine "Combine157"
combine "Combine158"
fillet "Fillet240" radius 0.5
extrude "Extrude208" cut sketch "Sketch202" profile of L1 L6 L7 L8 L9 against normal blind 2
fillet "Fillet241" radius 0.5
fillet "Fillet242" radius 0.5
chamfer "Chamfer94" distance 1
mirror "Mirror45" mirrorStitchTolerance 0.1 bodies "Furnish_L"
sketch "Sketch203" plane through (0, 59.1873, 0) normal (0, -1, 0) x axis (1, 0, 0)
  line L1 (0, 3.4503) -> (0, 5.4503)
  line L2 (0, 19.4503) -> (0, 21.4503)
  arc A1 centre (0, 12.4503) radius 9 clockwise from (0, 21.4503) to (0, 3.4503)
  arc A2 centre (0, 12.4503) radius 7 clockwise from (0, 19.4503) to (0, 5.4503)
  circle C1 centre (0, 12.4503) radius 9.0739
  circle C2 centre (0, 12.4503) radius 7.1031
  circle C3 centre (0, 12.4503) radius 10.3256
  concentric A1 C1
  concentric C1 C2
  concentric C2 C3
fillet "Fillet243" radius 1.25
extrude "Extrude209" new body sketch "Sketch203" profile of C1 C3 against normal blind 2
extrude "Extrude210" new body sketch "Sketch203" profile of L1 A1 L2 C1 C2 C3 along normal blind 2 bodies "SaftyTip"
combine "Combine159"
fillet "Fillet244" radius 0.5
sketch "Sketch204" plane through (0, 60, 0) normal (0, -1, 0) x axis (1, 0, 0)
  line L1 (-8.7, 24.7) -> (-8.7, 19.7046)
  line L2 (8.7, 24.7) -> (-8.7, 24.7)
  line L3 (8.7, 19.7046) -> (8.7, 24.7)
  line L4 (10.082, 18.7) -> (9.2104, 18.9939)
  line L5 (11.8671, 18.7) -> (10.082, 18.7)
  line L6 (13, 8.8275) -> (13, 13.5)
  line L7 (14.5, 8.8275) -> (13, 8.8275)
  line L8 (14.5, 19.7929) -> (14.5, 8.8275)
  line L9 (6.7929, 27.5) -> (14.5, 19.7929)
  line L10 (5.1086, 27.5) -> (6.7929, 27.5)
  line L11 (-6.7929, 27.5) -> (-5.1086, 27.5)
  line L12 (-14.5, 19.7929) -> (-6.7929, 27.5)
  line L13 (-14.5, 8.8275) -> (-14.5, 19.7929)
  line L14 (-13, 8.8275) -> (-14.5, 8.8275)
  line L15 (-13, 13.5) -> (-13, 8.8275)
  line L16 (-10.082, 18.7) -> (-11.8671, 18.7)
  line L17 (-9.2104, 18.9939) -> (-10.082, 18.7)
  line L18 (-1.4696, 25.2232) -> (1.4696, 25.2232)
  line L19 (-1.4696, 31.542) -> (-1.4696, 25.2232)
  line L20 (1.4696, 31.542) -> (-1.4696, 31.542)
  line L21 (1.4696, 25.2232) -> (1.4696, 31.542)
  line L22 (-1.4696, 31.542) -> (1.4696, 25.2232)
  line L23 (1.4696, 31.542) -> (-1.4696, 25.2232)
  arc A1 centre (-9.45, 19.7046) radius 0.75 clockwise from (-8.7, 19.7046) to (-9.2104, 18.9939)
  arc A2 centre (9.45, 19.7046) radius 0.75 clockwise from (9.2104, 18.9939) to (8.7, 19.7046)
  arc A3 centre (0.5, 13.5) radius 12.5 clockwise from (11.8671, 18.7) to (13, 13.5)
  arc A4 centre (0, 40) radius 13.5036 clockwise from (5.1086, 27.5) to (-5.1086, 27.5)
  arc A5 centre (-0.5, 13.5) radius 12.5 clockwise from (-13, 13.5) to (-11.8671, 18.7)
  point P33 (0, 28.3826)
  horizontal L18
  perpendicular L18 L19
  parallel L18 L20
  parallel L19 L21
  coincident L22 P33
  coincident L23 P33
extrude "Extrude211" add sketch "Sketch204" profile of A4 L19 L20 L21 blind -14 from offset -7
move_face "MoveFace304"
fillet "Fillet245" radius 2.5
fillet "Fillet246" radius 0.5
sketch "Sketch205" plane through (0, 45.6214, -167.8868) normal (0, 0.2622, -0.965) x axis (-1, 0, 0)
  line L1 (-9.2, 161.7683) -> (-9.2, 188.1258)
  line L2 (-8.4, 160.3469) -> (-8.7607, 160.7076)
  line L3 (-8.4, 157.7469) -> (-8.4, 160.3469)
  line L4 (4.4, 153.7469) -> (-4.4, 153.7469)
  line L5 (8.4, 160.3469) -> (8.4, 157.7469)
  line L6 (8.7607, 160.7076) -> (8.4, 160.3469)
  line L7 (9.2, 188.1258) -> (9.2, 161.7683)
  line L8 (8.4, 189.5471) -> (8.7607, 189.1864)
  line L9 (8.4, 192.1471) -> (8.4, 189.5471)
  line L10 (-4.4, 196.1472) -> (4.4, 196.1472)
  line L11 (-8.4, 189.5471) -> (-8.4, 192.1471)
  line L12 (-8.7607, 189.1864) -> (-8.4, 189.5471)
  line L13 (6.75, 157.4469) -> (6.75, 192.4471)
  line L14 (-4.75, 155.4469) -> (4.75, 155.4469)
  line L15 (-6.75, 192.4471) -> (-6.75, 157.4469)
  line L16 (4.75, 194.4471) -> (-4.75, 194.4471)
  line L17 (0, 197.5869) -> (0, 214.4591)
  line L18 (4.7607, 197.5869) -> (0, 197.5869)
  line L19 (9.7607, 190.4748) -> (9.7607, 192.5869)
  line L20 (10.566, 161.1663) -> (10.566, 188.8707)
  line L21 (9.7607, 157.431) -> (9.7607, 159.5622)
  line L22 (0, 152.4309) -> (4.7607, 152.4309)
  line L23 (0, 142.1861) -> (0, 152.4309)
  line L24 (3, 142.1861) -> (0, 142.1861)
  line L25 (11, 203.2743) -> (11, 150.1861)
  line L26 (11, 203.2743) -> (11, 203.3859)
  curve K1 (11, 203.3859) -> (0, 214.4591)
  line L27 (0, 214.4591) -> (0, 197.5869)
  curve K2 (0, 214.4591) -> (-11, 203.3859)
  line L28 (-11, 203.3859) -> (-11, 203.2743)
  line L29 (-11, 150.1861) -> (-11, 203.2743)
  line L30 (0, 142.1861) -> (-3, 142.1861)
  line L31 (0, 152.4309) -> (0, 142.1861)
  line L32 (-4.7607, 152.4309) -> (0, 152.4309)
  line L33 (-9.7607, 159.5622) -> (-9.7607, 157.431)
  line L34 (-10.566, 188.8707) -> (-10.566, 161.1663)
  line L35 (-9.7607, 192.5869) -> (-9.7607, 190.4748)
  line L36 (0, 197.5869) -> (-4.7607, 197.5869)
  closed curve K3 centre (-7.7, 188.1258)
  closed curve K4 centre (-7.7, 161.7683)
  closed curve K5 centre (-4.4, 157.7469)
  closed curve K6 centre (4.4, 157.7469)
  closed curve K7 centre (7.7, 161.7683)
  closed curve K8 centre (7.7, 188.1258)
  closed curve K9 centre (4.4, 192.1471)
  closed curve K10 centre (-4.4, 192.1471)
  closed curve K11 centre (4.75, 157.4469)
  closed curve K12 centre (-4.75, 157.4469)
  closed curve K13 centre (-4.75, 192.4471)
  closed curve K14 centre (4.75, 192.4471)
  closed curve K15 centre (4.7607, 192.5869)
  closed curve K16 centre (8.566, 188.8707)
  closed curve K17 centre (8.566, 161.1663)
  closed curve K18 centre (4.7607, 157.431)
  closed curve K19 centre (3, 150.1861)
  closed curve K20 centre (-3, 150.1861)
  closed curve K21 centre (-4.7607, 157.431)
  closed curve K22 centre (-8.566, 161.1663)
  closed curve K23 centre (-8.566, 188.8707)
  closed curve K24 centre (-4.7607, 192.5869)
extrude "Extrude212" new body sketch "Sketch205" profile of K3 L1 K4 L2 L3 K5 L4 K6 L5 L6 K7 L7 K8 L8 L9 K9 L10 K10 L11 L12 L17 L18 K15 L19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 against normal blind 4
sketch "Sketch206" plane through (0, 45.6214, -167.8868) normal (0, 0.2622, -0.965) x axis (-1, 0, 0)
  line L1 (-8.4, 189.5471) -> (-8.7607, 189.1864)
  line L2 (-8.4, 192.1471) -> (-8.4, 189.5471)
  line L3 (4.4, 196.1472) -> (-4.4, 196.1472)
  line L4 (8.4, 189.5471) -> (8.4, 192.1471)
  line L5 (8.7607, 189.1864) -> (8.4, 189.5471)
  line L6 (9.2, 161.7683) -> (9.2, 188.1258)
  line L7 (8.4, 160.3469) -> (8.7607, 160.7076)
  line L8 (8.4, 157.7469) -> (8.4, 160.3469)
  line L9 (-4.4, 153.7469) -> (4.4, 153.7469)
  line L10 (-8.4, 160.3469) -> (-8.4, 157.7469)
  line L11 (-8.7607, 160.7076) -> (-8.4, 160.3469)
  line L12 (-9.2, 188.1258) -> (-9.2, 161.7683)
  line L13 (-11, 150.1861) -> (-11, 203.3859)
  line L14 (3, 142.1861) -> (-3, 142.1861)
  line L15 (11, 203.3859) -> (11, 150.1861)
  curve K1 (11, 203.3859) -> (0, 214.4591)
  curve K2 (0, 214.4591) -> (-11, 203.3859)
  closed curve K3 centre (-4.4, 192.1471)
  closed curve K4 centre (4.4, 192.1471)
  closed curve K5 centre (7.7, 188.1258)
  closed curve K6 centre (7.7, 161.7683)
  closed curve K7 centre (4.4, 157.7469)
  closed curve K8 centre (-4.4, 157.7469)
  closed curve K9 centre (-7.7, 161.7683)
  closed curve K10 centre (-7.7, 188.1258)
  closed curve K11 centre (-3, 150.1861)
  closed curve K12 centre (3, 150.1861)
extrude "Extrude213" new body sketch "Sketch206" along normal blind 1
combine "Combine160"
chamfer "Chamfer95" distance 2
fillet "Fillet247" radius 1.5
move_face "MoveFace305"
fillet "Fillet248" radius 0.75
sketch "Sketch207" plane through (-12, 0, 0) normal (-1, 0, 0) x axis (0, -1, 0)
  line L1 (-62.1873, 16) -> (-62.1873, 4.4251)
  line L2 (-205.8331, 16) -> (-62.1873, 16)
  line L3 (-221.2152, 0.6179) -> (-205.8331, 16)
  line L4 (-220.6993, -4.9724) -> (-221.2152, 0.6179)
  line L5 (-206.6662, -17.6022) -> (-220.6993, -4.9724)
  line L6 (-206.6662, -40.176) -> (-206.6662, -17.6022)
  curve K1 (-206.6662, -40.176) -> (-240.3598, -109.3449)
  line L7 (-189.1188, -123.2274) -> (-240.3598, -109.3449)
  line L8 (-186.4094, -113.2266) -> (-189.1188, -123.2274)
  line L9 (-189.1513, -106.0289) -> (-186.4094, -113.2266)
  line L10 (-169.5112, -33.2283) -> (-189.2884, -97.8715)
  curve K2 (-169.5112, -33.2283) -> (-143.7253, -13.6797)
  line L11 (-94.4207, -13.6797) -> (-143.7253, -13.6797)
  curve K3 (-94.4207, -13.6797) -> (-62.1781, 2.9716)
  curve K4 (-62.1781, 2.9716) -> (-62.1873, 4.4251)
  line L12 (-152.7089, 8.4519) -> (-152.3198, 8.841)
  line L13 (-153.3679, 3.9459) -> (-153.3679, 6.8609)
  line L14 (-156.6179, 2.4459) -> (-154.8679, 2.4459)
  line L15 (-159.3679, 12.5) -> (-159.3679, 5.1959)
  line L16 (-102, 15.5) -> (-156.3679, 15.5)
  line L17 (-99.5, 12) -> (-99.5, 13)
  line L18 (-150.7288, 9.5) -> (-102, 9.5)
  arc A1 centre (-177.9477, -101.7609) radius 11.9891 clockwise from (-189.1513, -106.0289) to (-189.2884, -97.8715)
  arc A2 centre (-150.7288, 7.25) radius 2.25 clockwise from (-152.3198, 8.841) to (-150.7288, 9.5)
  arc A3 centre (-151.1179, 6.8609) radius 2.25 clockwise from (-153.3679, 6.8609) to (-152.7089, 8.4519)
  arc A4 centre (-154.8679, 3.9459) radius 1.5 clockwise from (-153.3679, 3.9459) to (-154.8679, 2.4459)
  arc A5 centre (-156.6179, 5.1959) radius 2.75 clockwise from (-156.6179, 2.4459) to (-159.3679, 5.1959)
  arc A6 centre (-156.3679, 12.5) radius 3 clockwise from (-159.3679, 12.5) to (-156.3679, 15.5)
  arc A7 centre (-102, 13) radius 2.5 clockwise from (-102, 15.5) to (-99.5, 13)
  arc A8 centre (-102, 12) radius 2.5 clockwise from (-99.5, 12) to (-102, 9.5)
  circle C1 centre (-80, -5) radius 4.5
  circle C2 centre (-133.5549, -4.0047) radius 3.2417
  circle C3 centre (-133.5549, -4.0047) radius 1.4
  concentric C2 C3
  dimension "d1653" diameter C3 = 2.8
extrude "Extrude214" cut sketch "Sketch207" profile of C3 against normal blind 35
chamfer "Chamfer96" distance 1.7
sketch "Sketch208" plane through (-12, 0, 0) normal (-1, 0, 0) x axis (0, -1, 0)
  line L1 (-152.7089, 8.4519) -> (-152.3198, 8.841)
  line L2 (-153.3679, 3.9459) -> (-153.3679, 6.8609)
  line L3 (-156.6179, 2.4459) -> (-154.8679, 2.4459)
  line L4 (-159.3679, 12.5) -> (-159.3679, 5.1959)
  line L5 (-102, 15.5) -> (-156.3679, 15.5)
  line L6 (-99.5, 12) -> (-99.5, 13)
  line L7 (-150.7288, 9.5) -> (-102, 9.5)
  line L8 (-62.1873, 16) -> (-62.1873, 4.4251)
  line L9 (-205.8331, 16) -> (-62.1873, 16)
  line L10 (-221.2152, 0.6179) -> (-205.8331, 16)
  line L11 (-220.6993, -4.9724) -> (-221.2152, 0.6179)
  line L12 (-206.6662, -17.6022) -> (-220.6993, -4.9724)
  line L13 (-206.6662, -40.176) -> (-206.6662, -17.6022)
  curve K1 (-206.6662, -40.176) -> (-240.3598, -109.3449)
  line L14 (-189.1188, -123.2274) -> (-240.3598, -109.3449)
  line L15 (-186.4094, -113.2266) -> (-189.1188, -123.2274)
  line L16 (-189.1513, -106.0289) -> (-186.4094, -113.2266)
  line L17 (-169.5112, -33.2283) -> (-189.2884, -97.8715)
  curve K2 (-169.5112, -33.2283) -> (-143.7253, -13.6797)
  line L18 (-94.4207, -13.6797) -> (-143.7253, -13.6797)
  curve K3 (-94.4207, -13.6797) -> (-62.1781, 2.9716)
  curve K4 (-62.1781, 2.9716) -> (-62.1873, 4.4251)
  circle C1 centre (-80, -5) radius 4.5
  arc A1 centre (-150.7288, 7.25) radius 2.25 clockwise from (-152.3198, 8.841) to (-150.7288, 9.5)
  arc A2 centre (-151.1179, 6.8609) radius 2.25 clockwise from (-153.3679, 6.8609) to (-152.7089, 8.4519)
  arc A3 centre (-154.8679, 3.9459) radius 1.5 clockwise from (-153.3679, 3.9459) to (-154.8679, 2.4459)
  arc A4 centre (-156.6179, 5.1959) radius 2.75 clockwise from (-156.6179, 2.4459) to (-159.3679, 5.1959)
  arc A5 centre (-156.3679, 12.5) radius 3 clockwise from (-159.3679, 12.5) to (-156.3679, 15.5)
  arc A6 centre (-102, 13) radius 2.5 clockwise from (-102, 15.5) to (-99.5, 13)
  arc A7 centre (-102, 12) radius 2.5 clockwise from (-99.5, 12) to (-102, 9.5)
  arc A8 centre (-177.9477, -101.7609) radius 11.9891 clockwise from (-189.1513, -106.0289) to (-189.2884, -97.8715)
  circle C2 centre (-133.5549, -4.0047) radius 3.1
  circle C3 centre (-240, -95) radius 1.4
  dimension "d1657" diameter C3 = 2.8
extrude "Extrude215" cut sketch "Sketch208" profile of C3 against normal blind 18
